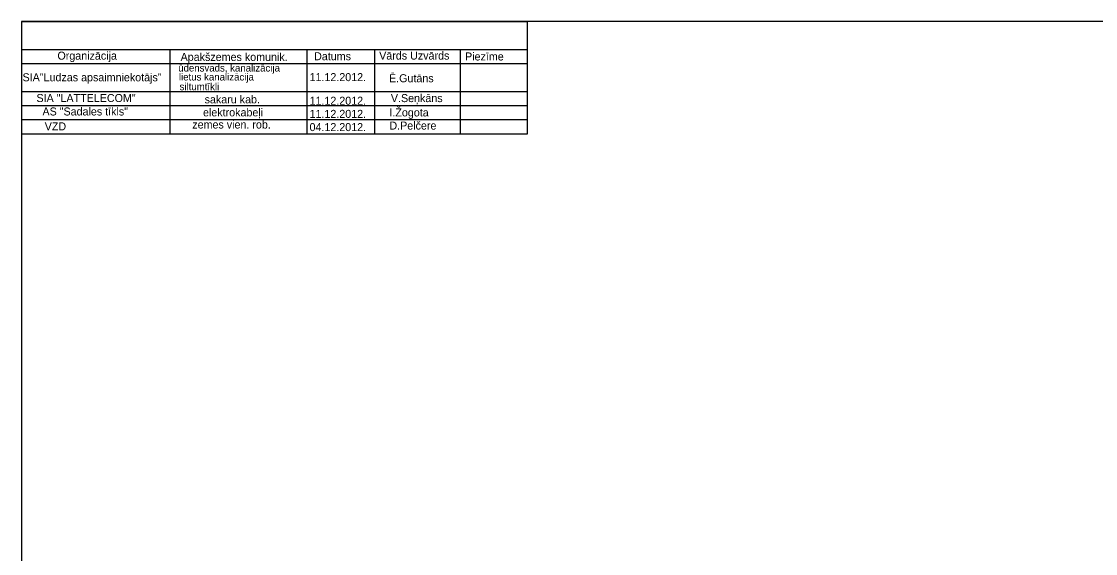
# Model space of a CAD drawing. Extents: x 728492 to 729038, y 272968 to 273171.
# Drawn here: x 728492.2 to 728626.4, y 273085.8 to 273152.3 of the extents above; entities that cross this region are included whole.
import ezdxf

# ---------------------------------------------------------------- set-up
doc = ezdxf.new("R2010")
doc.units = 0
doc.layers.add('RAMI_PLAN_####_TKST_#', color=7, linetype='Continuous')

msp = doc.modelspace()

# ---------------------------------------------------------------- linework, layer by layer
at = {"layer": 'RAMI_PLAN_####_TKST_#'}
for p, q in [((728492.23, 273152.29), (728555.45, 273152.29)), ((728492.23, 273148.79), (728555.45, 273148.79)), ((728510.79, 273138.24), (728510.79, 273148.65)), ((728527.92, 273138.24), (728527.92, 273148.79)), ((728536.37, 273138.24), (728536.37, 273148.7)), ((728547.1, 273138.24), (728547.1, 273148.74)), ((728492.23, 273147.04), (728555.45, 273147.04)), ((728492.23, 273143.55), (728555.45, 273143.55)), ((728492.23, 273141.8), (728555.45, 273141.8)), ((728492.23, 273140.06), (728555.45, 273140.06)), ((728492.23, 273138.24), (728555.45, 273138.24))]:
    msp.add_line(p, q, dxfattribs=at)
msp.add_lwpolyline([(728492.23, 273152.29), (728492.23, 272968.26), (728765.31, 272968.26), (728765.31, 273152.29)], close=True, dxfattribs=at)
for points in [[(728492.23, 273152.29), (728492.23, 273134.31)], [(728555.45, 273138.24), (728555.45, 273152.29)]]:
    msp.add_lwpolyline(points, dxfattribs=at)

# ---------------------------------------------------------------- texts
for s, height, rotation, p in [('Organizācija', 1, 359.9999, (728496.72, 273147.52)), ('Apakšzemes komunik.', 1, 359.9999, (728512.11, 273147.36)), ('Datums', 1, 359.9999, (728528.79, 273147.45)), ('Vārds Uzvārds', 1, 359.9999, (728536.92, 273147.53)), ('Piezīme', 1, 359.9999, (728547.65, 273147.42)), ('ūdensvads, kanalizācija', 0.9, 359.9999, (728511.81, 273146.04)), ('SIA"Ludzas apsaimniekotājs"', 1, 359.9997, (728492.36, 273144.82)), ('lietus kanalizācija', 0.9, 359.9997, (728511.9, 273144.92)), ('11.12.2012.', 1, 359.9999, (728528.22, 273144.84)), ('Ē.Gutāns', 1, 359.9997, (728538.15, 273144.7)), ('siltumtīkli', 0.9, 359.9997, (728511.98, 273143.71)), ('SIA "LATTELECOM"', 1, 359.9997, (728494.1, 273142.23)), ('sakaru kab.', 1, 359.9999, (728515.11, 273142.06)), ('11.12.2012.', 1, 359.9999, (728528.22, 273141.89)), ('V.Seņkāns', 1, 359.9997, (728538.38, 273142.22)), ('AS "Sadales tīkls"', 1, 359.9997, (728494.85, 273140.55)), ('elektrokabeļi', 1, 359.9997, (728514.91, 273140.44)), ('11.12.2012.', 1, 359.9999, (728528.22, 273140.25)), ('I.Žogota', 1, 359.9997, (728538.2, 273140.43)), ('zemes vien. rob.', 1, 359.9997, (728513.57, 273138.92)), ('D.Pelčere', 1, 359.9997, (728538.2, 273138.79)), ('VZD', 1, 359.9997, (728495.13, 273138.69)), ('04.12.2012.', 1, 359.9999, (728528.22, 273138.6))]:
    msp.add_text(s, height=height, rotation=rotation, dxfattribs=at).set_placement(p)

doc.saveas('drawing.dxf')
